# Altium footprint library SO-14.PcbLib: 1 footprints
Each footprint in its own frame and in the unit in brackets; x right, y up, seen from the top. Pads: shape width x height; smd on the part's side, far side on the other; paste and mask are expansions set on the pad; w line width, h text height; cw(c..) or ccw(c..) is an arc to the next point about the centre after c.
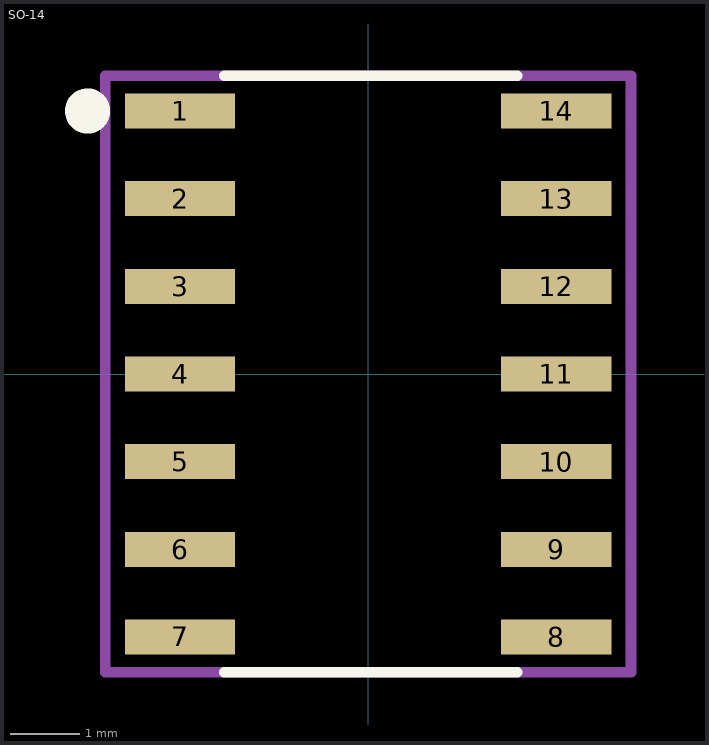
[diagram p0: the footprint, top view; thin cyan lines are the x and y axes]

## SO-14 [mil]
pads (14):
  rect 62.99x20 smd: 1(-107.25,150) 2(-107.25,100) 3(-107.25,50) 4(-107.25,0) 5(-107.25,-50) 6(-107.25,-100) 7(-107.25,-150) 8(107.25,-150) 9(107.25,-100) 10(107.25,-50) 11(107.25,0) 12(107.25,50) 13(107.25,100) 14(107.25,150)
Top Overlay:
  circle w13.78: c-160,150 r6
  lines w6: -82,-170 85,-170 ; -82,170 85,170
Mechanical 15:
  lines w6: -150,-170 -150,170 -88.5,170 88.5,170 150,170 150,-170 88.5,-170 -88.5,-170 -150,-170
3D body "SO-14_STM.step": height 69.09, standoff 0, extent -122.01,-172.01 122.01,172.01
